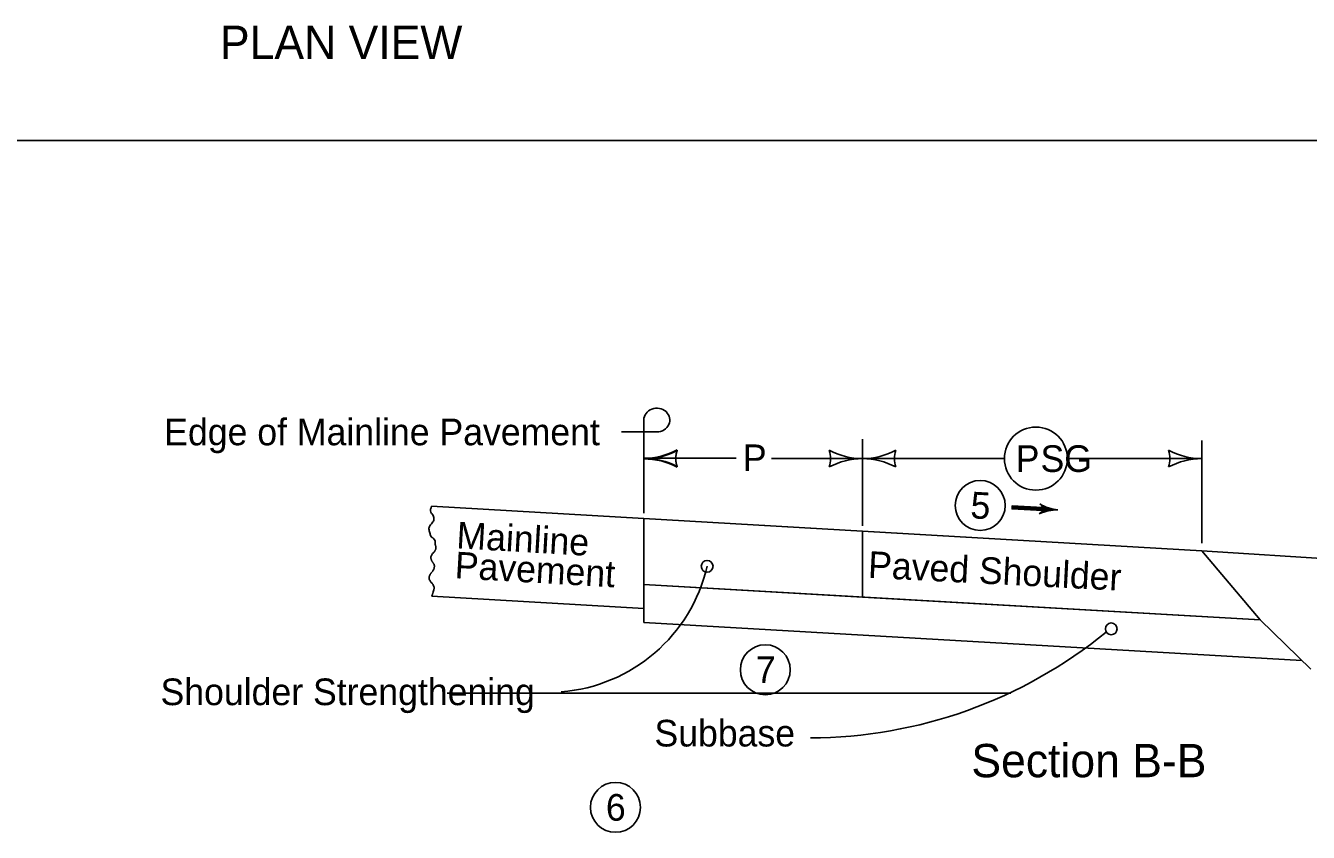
# Model space of a CAD drawing. Extents: x 10133 to 81668, y 7924 to 12229.
# Drawn here: x 11037 to 11808, y 8941 to 9425 of the extents above; entities that cross this region are included whole.
import ezdxf

# ---------------------------------------------------------------- set-up
doc = ezdxf.new("R2010")
doc.units = 0
for name, color, linetype in [('dsnTextFinalPlan', 7, 'Continuous'), ('Level 12', 7, 'Continuous'), ('Level 4', 7, 'Continuous'), ('Level 5', 7, 'Continuous'), ('Level 6', 7, 'Continuous')]:
    doc.layers.add(name, color=color, linetype=linetype)

msp = doc.modelspace()

# ---------------------------------------------------------------- linework, layer by layer
at = {"layer": 'dsnTextFinalPlan'}
for p, q in [((11281.22, 9136.81), (11408.68, 9129.39)), ((11408.68, 9129.39), (11408.68, 9075.38)), ((11408.68, 9129.39), (11743.82, 9109.9)), ((11540.06, 9121.75), (11540.06, 9082.22)), ((11743.82, 9109.9), (11540.06, 9121.75)), ((11540.06, 9121.75), (11540.06, 9082.22)), ((11743.82, 9109.9), (11778.86, 9068.46)), ((11743.82, 9109.9), (11878.66, 9101.51)), ((11778.86, 9068.46), (11743.82, 9109.9)), ((11778.86, 9068.46), (11408.68, 9089.79)), ((11281.25, 9082.79), (11408.68, 9075.38)), ((11540.06, 9082.22), (11778.86, 9068.46)), ((11408.68, 9075.38), (11408.68, 9066.96)), ((11408.68, 9066.96), (11803.88, 9044.17)), ((11778.86, 9068.46), (11809.39, 9038.83)), ((11290.63, 9024.47), (11629.13, 9024.47))]:
    msp.add_line(p, q, dxfattribs=at)
msp.add_lwpolyline([(11540.06, 9082.22), (11408.68, 9089.79), (11408.68, 9129.39), (11540.06, 9121.75)], close=True, dxfattribs=at)
for points in [[(11281.22, 9136.81), (11280.71, 9133.2), (11281.76, 9131.7), (11282.62, 9129.4), (11282.01, 9127.34), (11280.11, 9124.97), (11279.59, 9123.06), (11280.11, 9120.77), (11280.98, 9118.39), (11282.01, 9117.68), (11283.4, 9115.15), (11283.39, 9114.31)], [(11281.43, 9097.2), (11281.64, 9097.44), (11281.84, 9097.7), (11282.19, 9098.26), (11282.47, 9098.85), (11282.59, 9099.16), (11282.69, 9099.48), (11282.82, 9100.09), (11282.87, 9100.71), (11282.82, 9101.3), (11282.76, 9101.58), (11282.72, 9101.71), (11282.68, 9101.84), (11282.47, 9102.22), (11282.19, 9102.58), (11281.89, 9102.95), (11281.64, 9103.35), (11281.5, 9103.63), (11281.36, 9103.92), (11281.1, 9104.49), (11280.9, 9105.06), (11280.83, 9105.35), (11280.77, 9105.65), (11280.76, 9105.77), (11280.76, 9105.9), (11280.91, 9106.68), (11281.12, 9107.19), (11281.38, 9107.7), (11281.82, 9108.34), (11282.34, 9108.89), (11282.86, 9109.43), (11283.09, 9109.74), (11283.29, 9110.08), (11283.49, 9110.55), (11283.65, 9111.03), (11283.75, 9111.5), (11283.78, 9111.74), (11283.8, 9111.86), (11283.81, 9111.98), (11283.76, 9112.49), (11283.61, 9113), (11283.56, 9113.13), (11283.5, 9113.26), (11283.45, 9113.38), (11283.43, 9113.52), (11283.39, 9114.31)], [(11281.43, 9097.2), (11281.21, 9096.96), (11280.97, 9096.72), (11280.73, 9096.48), (11280.55, 9096.21), (11280.41, 9095.93), (11280.27, 9095.65), (11280.01, 9095.07), (11279.9, 9094.79), (11279.8, 9094.5), (11279.73, 9094.21), (11279.7, 9094.06), (11279.68, 9093.92), (11279.69, 9093.4), (11279.82, 9092.89), (11280.03, 9092.37), (11280.29, 9091.86), (11280.73, 9091.22), (11281.25, 9090.68), (11281.77, 9090.13), (11282, 9089.82), (11282.2, 9089.48), (11282.6, 9088.54), (11282.71, 9088.06), (11282.72, 9087.58), (11282.68, 9087.29), (11282.63, 9087), (11282.58, 9086.72), (11282.51, 9086.43), (11282.2, 9085.28), (11282.02, 9084.67), (11281.82, 9084.07), (11281.6, 9083.48), (11281.47, 9083.19), (11281.33, 9082.91), (11281.25, 9082.79)]]:
    msp.add_spline(points, degree=3, dxfattribs=at)
at = {"layer": 'Level 12'}
for centre in [(11610.77, 9137.2), (11481.65, 9038.53), (11391.6, 8955.93)]:
    msp.add_circle(centre, 15, dxfattribs=at)
at = {"layer": 'Level 4'}
msp.add_line((12307.76, 9356.36), (10152.18, 9356.36), dxfattribs=at)
for centre in [(11446.69, 9100.64), (11689.43, 9063.1)]:
    msp.add_circle(centre, 3.54, dxfattribs=at)
at = {"layer": 'Level 5'}
for p, q in [((11540.06, 9176.92), (11540.06, 9124.9)), ((11743.9, 9114.46), (11743.9, 9176.14)), ((11464.18, 9165.53), (11408.7, 9165.53)), ((11485.3, 9165.31), (11540.06, 9165.31)), ((11540.06, 9165.31), (11625.23, 9165.31)), ((11663.1, 9165.31), (11743.9, 9165.31))]:
    msp.add_line(p, q, dxfattribs=at)
msp.add_circle((11644.17, 9165.31), 18.93, dxfattribs=at)
for centre, radius, start, end in [((11408.68, 9207.65), 42.5, 270, 298.07249), ((11408.7, 9208.03), 42.5, 270, 298.07249), ((11444.32, 9165.15), 16.42, 162.26665, 197.73335), ((11444.34, 9165.53), 16.42, 162.26665, 197.73335), ((11504.42, 9165.31), 16.42, 342.26665, 17.73335), ((11540.06, 9207.81), 42.5, 241.92751, 270), ((11540.06, 9207.81), 42.5, 270, 298.07249), ((11540.06, 9207.81), 42.5, 270, 298.07249), ((11575.69, 9165.31), 16.42, 162.26665, 197.73335), ((11575.69, 9165.31), 16.42, 162.26665, 197.73335), ((11708.27, 9165.31), 16.42, 342.26665, 17.73335), ((11743.9, 9207.81), 42.5, 241.92751, 270), ((11408.68, 9122.65), 42.5, 61.92751, 90), ((11408.7, 9123.03), 42.5, 61.92751, 90), ((11540.06, 9122.81), 42.5, 90, 118.07249), ((11540.06, 9122.81), 42.5, 61.92751, 90), ((11540.06, 9122.81), 42.5, 61.92751, 90), ((11743.9, 9122.81), 42.5, 90, 118.07249), ((11351.46, 9122.76), 97.76, 274.44201, 346.92302), ((11508.11, 9279.69), 282.03, 270.13198, 309.22072)]:
    msp.add_arc(centre, radius, start, end, dxfattribs=at)
at = {"layer": 'Level 6'}
for p, q in [((11408.68, 9168.47), (11408.68, 9189.33)), ((11395.31, 9181.32), (11403.99, 9181.32)), ((11416.49, 9181.32), (11403.99, 9181.32)), ((11408.68, 9132.54), (11408.68, 9168.47)), ((11648.15, 9135.04), (11629.94, 9136.09)), ((11648.05, 9134.1), (11648.05, 9134.1)), ((11648.16, 9136.05), (11648.16, 9136.05))]:
    msp.add_line(p, q, dxfattribs=at)
for points in [[(11648.18, 9135.98), (11630.01, 9137.03), (11629.88, 9135.15), (11648.05, 9134.1), (11648.1, 9135.72), (11630.23, 9136.81), (11630.17, 9135.31), (11647.66, 9134.36), (11647.79, 9135.48), (11630.46, 9136.55), (11630.44, 9135.55), (11647.45, 9134.56), (11647.54, 9135.27), (11630.65, 9136.33), (11630.64, 9135.76), (11647.24, 9134.83)], [(11647.77, 9137.24), (11648.47, 9136.07), (11648.44, 9134.42), (11647.69, 9133.03), (11650.44, 9133.89), (11653.63, 9134.54), (11654.53, 9134.68), (11652.29, 9135.22), (11649.06, 9136.45), (11648.12, 9136.99), (11648.24, 9133.48), (11653.19, 9134.69), (11648.55, 9136.27), (11648.56, 9133.85), (11651.96, 9134.78), (11648.96, 9135.65), (11648.73, 9134.26), (11650.89, 9134.76), (11649.3, 9135.27), (11649.16, 9134.61), (11649.95, 9134.78)]]:
    msp.add_lwpolyline(points, dxfattribs=at)
for centre, major_axis, start_param, end_param in [((11416.49, 9188.46), (-7.81, 0), 1.570796, 6.283185), ((11644.38, 9135.26), (3.88, 0), 5.202895, 7.237436), ((11659.44, 9154.68), (-22.17, 0), 0.954258, 1.478381), ((11656.65, 9114.26), (22.17, 0), 1.537172, 2.061295)]:
    msp.add_ellipse(centre, major_axis=major_axis, ratio=0.913811, start_param=start_param, end_param=end_param, dxfattribs=at)

# ---------------------------------------------------------------- texts
at = {"layer": 'Level 12'}
msp.add_text('5', height=16, rotation=356.69973, dxfattribs=at).set_placement((11604.55, 9129.55))
for s, p in [('7', (11475.94, 9030.53)), ('6', (11385.89, 8947.93))]:
    msp.add_text(s, height=16, dxfattribs=at).set_placement(p)
at = {"layer": 'Level 5'}
for s, p in [('P', (11468.18, 9157.79)), ('P', (11632.04, 9157.31)), ('SG', (11646.95, 9157.31))]:
    msp.add_text(s, height=16, dxfattribs=at).set_placement(p)
at = {"layer": 'Level 6'}
for s, height, p in [('PLAN VIEW', 20, (11154.04, 9405.26)), ('Edge of Mainline Pavement', 16, (11120.58, 9173.32)), ('Shoulder Strengthening', 16, (11118.36, 9017.29)), ('Subbase', 16, (11415.05, 8992.47)), ('Section B-B', 20, (11605.42, 8974))]:
    msp.add_text(s, height=height, dxfattribs=at).set_placement(p)
for s, rotation, p in [('Mainline', 356.73462, (11295.81, 9111.47)), ('Pavement', 356.73462, (11294.79, 9093.5)), ('Paved Shoulder ', 357.0678, (11543.08, 9093.8))]:
    msp.add_text(s, height=16, rotation=rotation, dxfattribs=at).set_placement(p)

doc.saveas('drawing.dxf')
